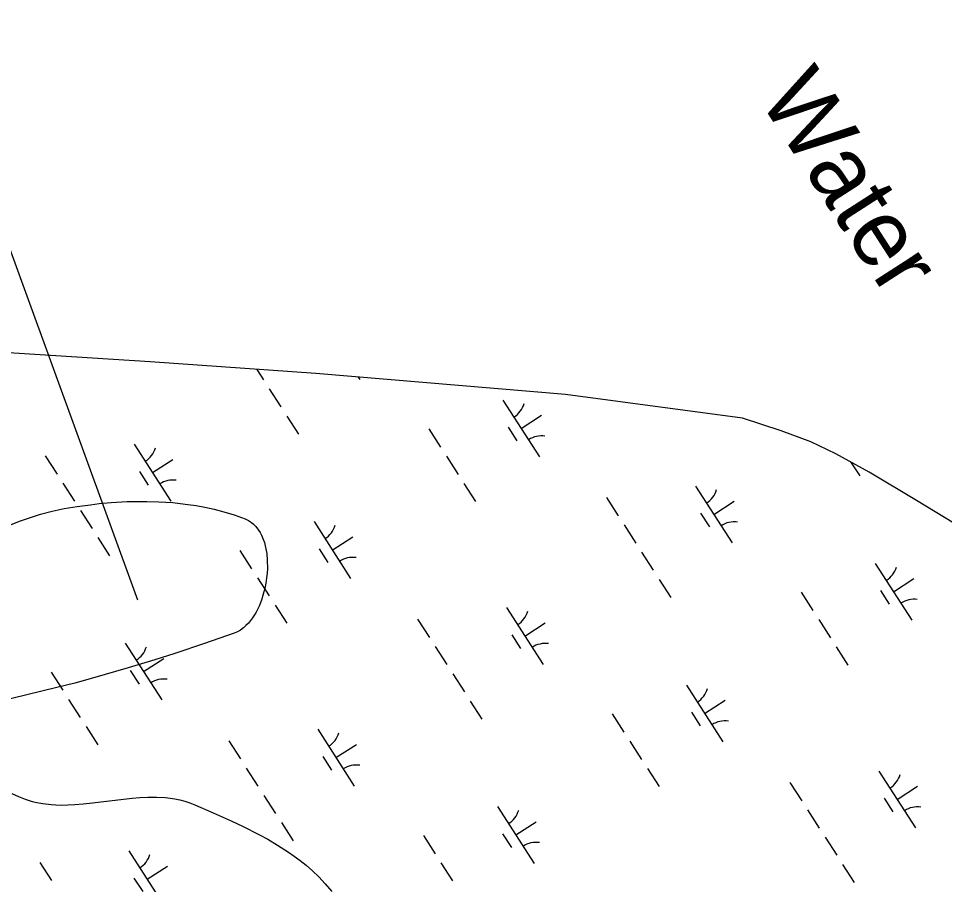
# Model space of a CAD drawing. Extents: x 3937982 to 3958556, y 219448 to 241894.
# Drawn here: x 3951560 to 3952246, y 225925 to 226566 of the extents above; entities that cross this region are included whole.
import ezdxf

# ---------------------------------------------------------------- set-up
doc = ezdxf.new("R2010")
doc.units = 0
for name, color, linetype in [('V-RIVR-IDEN', 7, 'Continuous'), ('V-SITE-VEGE', 7, 'Continuous'), ('V-TOPO-SHOR', 7, 'Continuous'), ('V-UTIL-LINE', 7, 'Continuous'), ('V-WETL-SWMP', 7, 'Continuous')]:
    doc.layers.add(name, color=color, linetype=linetype)

msp = doc.modelspace()

# ---------------------------------------------------------------- linework, layer by layer
at = {"layer": 'V-SITE-VEGE'}
for points in [[(3951504.654, 226171.256), (3951561.15, 226193.968), (3951568.687, 226196.616), (3951576.731, 226199.155), (3951585.325, 226201.466), (3951589.767, 226202.471), (3951594.352, 226203.366), (3951603.927, 226204.941), (3951613.661, 226206.278), (3951620.225, 226207.028), (3951629.049, 226207.831), (3951640.918, 226208.525), (3951647.737, 226208.711), (3951655.544, 226208.726), (3951664.474, 226208.468), (3951674.663, 226207.784), (3951680.084, 226207.245), (3951685.843, 226206.522), (3951691.958, 226205.588), (3951698.444, 226204.394), (3951705.309, 226202.889), (3951712.559, 226201.007), (3951720.198, 226198.674), (3951728.22, 226195.803), (3951730.747, 226194.613), (3951733.051, 226193.097), (3951734.464, 226191.92), (3951736.203, 226190.152), (3951738.257, 226187.472), (3951739.299, 226185.786)], [(3951739.299, 226185.786), (3951740.375, 226183.736), (3951741.456, 226181.242), (3951742.496, 226178.215), (3951743.443, 226174.553), (3951744.204, 226170.145), (3951744.682, 226164.89), (3951744.721, 226158.91), (3951744.532, 226155.572), (3951744.172, 226151.998), (3951743.606, 226148.201), (3951742.806, 226144.187), (3951741.728, 226139.989), (3951740.336, 226135.643), (3951738.577, 226131.213), (3951736.402, 226126.779), (3951735.16, 226124.633), (3951733.796, 226122.529), (3951732.306, 226120.49), (3951730.675, 226118.536), (3951728.9, 226116.693), (3951726.971, 226114.991), (3951724.875, 226113.465), (3951722.608, 226112.15), (3951720.159, 226111.093), (3951698.229, 226103.442), (3951676.166, 226096.168), (3951661.4, 226091.504), (3951641.667, 226085.498), (3951615.32, 226077.816), (3951602.157, 226074.217), (3951588.806, 226070.813), (3951544.154, 226059.951)], [(3951555.606, 225992.449), (3951560.482, 225990.081), (3951565.484, 225988.121), (3951570.54, 225986.579), (3951573.942, 225985.768), (3951578.505, 225984.935), (3951584.641, 225984.22), (3951588.167, 225983.995), (3951592.218, 225983.884), (3951596.867, 225983.929), (3951602.204, 225984.171), (3951608.324, 225984.652), (3951615.338, 225985.402), (3951634.057, 225987.83), (3951644.698, 225989.041), (3951650.338, 225989.504), (3951656.319, 225989.79), (3951662.649, 225989.807), (3951669.332, 225989.418), (3951672.752, 225989.027), (3951676.258, 225988.476), (3951679.848, 225987.732), (3951683.524, 225986.768), (3951687.284, 225985.549), (3951691.126, 225984.029), (3951704.498, 225978.229), (3951717.929, 225972.225), (3951726.823, 225968.037), (3951738.499, 225962.134), (3951745.032, 225958.56), (3951752.333, 225954.268), (3951760.416, 225949.052), (3951764.598, 225946.121), (3951768.946, 225942.871), (3951773.446, 225939.254), (3951778.074, 225935.213), (3951782.799, 225930.685), (3951787.577, 225925.59), (3951792.357, 225919.835)]]:
    msp.add_lwpolyline(points, dxfattribs=at)
at = {"layer": 'V-TOPO-SHOR'}
msp.add_lwpolyline([(3952253.034, 226192.534), (3952225.378, 226209.27), (3952190.417, 226230.385), (3952165.638, 226244.019), (3952147.128, 226252.75), (3952125.241, 226260.939), (3952096.587, 226270.391), (3951965.454, 226287.822), (3951780.513, 226303.374), (3951658.01, 226312.015), (3951545.135, 226319.152), (3951410.378, 226333.441), (3951287.58, 226348.059), (3951230.367, 226350.843), (3951201.253, 226350.412), (3951178.915, 226346.64)], dxfattribs=at)
at = {"layer": 'V-UTIL-LINE'}
msp.add_lwpolyline([(3950785.675, 228505.622), (3951648.465, 226135.699)], dxfattribs=at)
at = {"layer": 'V-WETL-SWMP'}
for p, q in [((3951658.01, 226312.015), (3951545.135, 226319.152)), ((3951780.513, 226303.374), (3951658.01, 226312.015)), ((3951736.915, 226306.449), (3951741.816, 226298.835)), ((3951965.453, 226287.821), (3951780.513, 226303.374)), ((3951811.996, 226300.726), (3951813.094, 226299.021)), ((3951746.146, 226292.108), (3951754.806, 226278.654)), ((3952096.587, 226270.391), (3951965.453, 226287.821)), ((3951919.161, 226283.766), (3951946.223, 226241.723)), ((3951759.136, 226271.927), (3951767.796, 226258.474)), ((3951932.692, 226262.744), (3951947.827, 226272.487)), ((3952125.241, 226260.94), (3952096.587, 226270.391)), ((3951864.295, 226262.369), (3951872.955, 226248.915)), ((3951922.957, 226263.614), (3951929.452, 226253.523)), ((3952147.127, 226252.749), (3952125.241, 226260.94)), ((3952165.637, 226244.018), (3952147.127, 226252.749)), ((3951646.164, 226251.035), (3951673.227, 226208.992)), ((3951580.299, 226242.44), (3951588.959, 226228.986)), ((3951659.695, 226230.013), (3951674.831, 226239.756)), ((3951877.285, 226242.188), (3951885.945, 226228.734)), ((3952190.416, 226230.385), (3952165.637, 226244.018)), ((3952176.628, 226237.971), (3952183.359, 226227.514)), ((3951649.96, 226230.883), (3951656.455, 226220.792)), ((3952225.378, 226209.271), (3952190.416, 226230.385)), ((3951593.289, 226222.259), (3951601.949, 226208.806)), ((3951890.275, 226222.007), (3951898.934, 226208.554)), ((3952061.727, 226220.076), (3952088.789, 226178.033)), ((3951995.862, 226211.481), (3952004.522, 226198.027)), ((3952075.258, 226199.054), (3952090.393, 226208.797)), ((3952253.034, 226192.534), (3952225.378, 226209.271)), ((3951606.279, 226202.079), (3951614.939, 226188.625)), ((3952065.523, 226199.923), (3952072.018, 226189.833)), ((3951779.294, 226193.737), (3951806.356, 226151.693)), ((3952008.852, 226191.3), (3952017.511, 226177.846)), ((3951619.269, 226181.898), (3951627.929, 226168.444)), ((3951792.825, 226172.715), (3951807.96, 226182.457)), ((3951724.427, 226172.339), (3951733.087, 226158.886)), ((3951783.09, 226173.584), (3951789.584, 226163.494)), ((3952021.841, 226171.119), (3952030.501, 226157.666)), ((3952194.856, 226162.777), (3952221.918, 226120.734)), ((3951737.417, 226152.159), (3951746.077, 226138.705)), ((3952034.831, 226150.939), (3952043.491, 226137.485)), ((3952208.387, 226141.756), (3952223.523, 226151.498)), ((3952139.99, 226141.38), (3952148.65, 226127.926)), ((3952198.652, 226142.625), (3952205.147, 226132.534)), ((3951750.407, 226131.978), (3951759.067, 226118.524)), ((3951921.859, 226130.046), (3951948.922, 226088.003)), ((3951855.994, 226121.451), (3951864.654, 226107.998)), ((3951935.391, 226109.025), (3951950.526, 226118.767)), ((3952152.98, 226121.199), (3952161.64, 226107.746)), ((3951925.655, 226109.894), (3951932.15, 226099.804)), ((3951639.426, 226103.707), (3951666.489, 226061.664)), ((3951868.984, 226101.271), (3951877.644, 226087.817)), ((3952165.97, 226101.019), (3952174.63, 226087.565)), ((3951652.957, 226082.685), (3951668.093, 226092.428)), ((3951584.56, 226082.31), (3951593.22, 226068.856)), ((3951643.222, 226083.555), (3951649.717, 226073.464)), ((3951881.974, 226081.09), (3951890.634, 226067.636)), ((3952054.989, 226072.748), (3952082.051, 226030.705)), ((3951597.55, 226062.129), (3951606.21, 226048.675)), ((3951894.964, 226060.909), (3951903.624, 226047.455)), ((3952068.52, 226051.726), (3952083.655, 226061.469)), ((3952000.123, 226051.351), (3952008.783, 226037.897)), ((3952058.785, 226052.595), (3952065.28, 226042.505)), ((3951610.54, 226041.948), (3951619.2, 226028.495)), ((3951781.992, 226040.017), (3951809.054, 225997.974)), ((3951716.127, 226031.422), (3951724.787, 226017.968)), ((3951795.523, 226018.995), (3951810.659, 226028.738)), ((3952013.112, 226031.17), (3952021.772, 226017.716)), ((3951785.788, 226019.864), (3951792.283, 226009.774)), ((3951729.117, 226011.241), (3951737.777, 225997.787)), ((3952026.102, 226010.989), (3952034.762, 225997.535)), ((3952197.555, 226009.058), (3952224.617, 225967.014)), ((3952131.69, 226000.463), (3952140.349, 225987.009)), ((3952211.086, 225988.036), (3952226.221, 225997.778)), ((3951742.107, 225991.06), (3951750.767, 225977.607)), ((3952201.35, 225988.905), (3952207.845, 225978.815)), ((3951915.121, 225982.718), (3951942.184, 225940.675)), ((3952144.679, 225980.282), (3952153.339, 225966.828)), ((3951755.097, 225970.88), (3951763.757, 225957.426)), ((3951928.653, 225961.697), (3951943.788, 225971.439)), ((3951860.255, 225961.321), (3951868.915, 225947.867)), ((3951918.917, 225962.566), (3951925.412, 225952.475)), ((3952157.669, 225960.101), (3952166.329, 225946.647)), ((3951642.125, 225949.987), (3951669.187, 225907.944)), ((3951576.26, 225941.392), (3951584.92, 225927.939)), ((3951655.656, 225928.966), (3951670.792, 225938.708)), ((3951873.245, 225941.14), (3951881.905, 225927.687)), ((3952170.659, 225939.92), (3952179.319, 225926.467)), ((3951645.921, 225929.835), (3951652.416, 225919.745))]:
    msp.add_line(p, q, dxfattribs=at)
for centre, start, end in [((3951917.942, 226286.099), 301.99668, 343.540338), ((3951947.842, 226239.647), 81.996677, 123.540335), ((3951644.945, 226253.368), 301.99668, 343.540338), ((3951674.845, 226206.916), 81.996677, 123.540335), ((3952060.507, 226222.409), 301.99668, 343.540338), ((3951778.074, 226196.069), 301.99668, 343.540338), ((3952090.407, 226175.957), 81.996677, 123.540335), ((3951807.974, 226149.617), 81.996677, 123.540335), ((3952193.637, 226165.11), 301.99668, 343.540338), ((3952223.537, 226118.658), 81.996677, 123.540335), ((3951920.64, 226132.379), 301.99668, 343.540338), ((3951950.54, 226085.927), 81.996677, 123.540335), ((3951638.207, 226106.04), 301.99668, 343.540338), ((3951668.107, 226059.588), 81.996677, 123.540335), ((3952053.769, 226075.081), 301.99668, 343.540338), ((3952083.669, 226028.629), 81.996677, 123.540335), ((3951780.773, 226042.35), 301.99668, 343.540338), ((3951810.673, 225995.898), 81.996677, 123.540335), ((3952196.335, 226011.39), 301.99668, 343.540338), ((3951913.902, 225985.051), 301.99668, 343.540338), ((3952226.235, 225964.939), 81.996677, 123.540335), ((3951943.802, 225938.599), 81.996677, 123.540335), ((3951640.906, 225952.32), 301.99668, 343.540338)]:
    msp.add_arc(centre, 17.623, start, end, dxfattribs=at)

# ---------------------------------------------------------------- texts
at = {"layer": 'V-RIVR-IDEN'}
msp.add_text('Water', height=49.9999, rotation=302.768556, dxfattribs=at).set_placement((3952107.679, 226507.572))

doc.saveas('drawing.dxf')
